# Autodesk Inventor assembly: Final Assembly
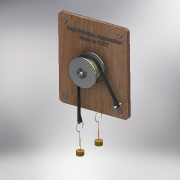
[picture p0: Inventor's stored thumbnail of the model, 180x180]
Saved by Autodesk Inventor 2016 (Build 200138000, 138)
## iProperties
Created: 2016-01
Part Number: Final Assembly
Document SubType Name: Assembly
Designer: Black Falcon
Author: Black Falcon
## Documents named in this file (10)
- E:\Learning Inventor\Shamim Boss's Project\Final Assembly.iam
- E:\Learning Inventor\Shamim Boss's Project\1. Disc.ipt
- E:\Learning Inventor\Shamim Boss's Project\6. Board.ipt
- E:\Learning Inventor\Shamim Boss's Project\7. Rod.ipt
- E:\Learning Inventor\Shamim Boss's Project\8.Belt Pin.ipt
- E:\Learning Inventor\Shamim Boss's Project\9. Long Belt.ipt
- E:\Learning Inventor\Shamim Boss's Project\5. Hook.ipt
- E:\Learning Inventor\Shamim Boss's Project\10. Ribbon.ipt
- C:\Users\Black Falcon\Documents\Inventor\Content Center Files\R2016\en-US\ANSI ASME B18.2.1(2)\ANSI_ASME B18.2.1 - 5_16-18 UNC - 1.5(2).ipt
- E:\Learning Inventor\Belt Friction Apparatus\Final Assembly\Design Accelerator\Bearing3.iam
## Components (14 placed, 9 different names)
1. 1. Disc:1 — Mate:5, Mate:18, Mate:20, Mate:21, Mate:22, Flush:24, Flush:25, Flush:26
2. 6. Board:1 — Mate:5, Flush:3, Mate:7, Mate:15, Flush:5, Flush:27
3. 7. Rod:1 — Mate:15, Mate:18, Mate:23, Mate:24, Flush:27
4. 8.Belt Pin:1 — Flush:3, Mate:7, Flush:5, Mate:19
5. 9. Long Belt:1 — Mate:19, Mate:20, Mate:21
6. 5. Hook:1
7. 10. Ribbon:1 — Mate:22, Flush:24
8. 5. Hook:2
9. Hex Bolt - Inch 5/16-18 UNC - 1.5:1
10. Hex Bolt - Inch 5/16-18 UNC - 1.5:2
11. Hex Bolt - Inch 5/16-18 UNC - 1.5:3
12. Hex Bolt - Inch 5/16-18 UNC - 1.5:4
13. Bearing:3 [sub-assembly] — Mate:23, Flush:25
14. Bearing:4 [sub-assembly] — Mate:24, Flush:26
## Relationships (16: Mate 10, Flush 6)
- Mate:5: 1. Disc:1 ↔ 6. Board:1
- Flush:3: 6. Board:1 ↔ 8.Belt Pin:1
- Mate:7: 6. Board:1 ↔ 8.Belt Pin:1
- Mate:15: 6. Board:1 ↔ 7. Rod:1
- Flush:5: 6. Board:1 ↔ 8.Belt Pin:1
- Mate:18: 1. Disc:1 ↔ 7. Rod:1
- Mate:19: 8.Belt Pin:1 ↔ 9. Long Belt:1
- Mate:20: 1. Disc:1 ↔ 9. Long Belt:1
- Mate:21: 1. Disc:1 ↔ 9. Long Belt:1
- Mate:22: 1. Disc:1 ↔ 10. Ribbon:1
- Flush:24: 1. Disc:1 ↔ 10. Ribbon:1
- Mate:23: 7. Rod:1 ↔ Bearing:3
- Flush:25: 1. Disc:1 ↔ Bearing:3
- Mate:24: 7. Rod:1 ↔ Bearing:4
- Flush:26: 1. Disc:1 ↔ Bearing:4
- Flush:27: 6. Board:1 ↔ 7. Rod:1
